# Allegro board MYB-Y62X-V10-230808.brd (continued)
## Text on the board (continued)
Ref Des/Silkscreen Bottom: LVDS0 | LVDS1 | SIM1 | SIM2 | CSI0
User.Comments: CR_3_1 | CR_1_1
Ref Des/Silkscreen Top: GND | TX | RX | VDD_12V | VDD_3V9 | VDD_5V | VDD_3V3 | VDD_1V8 | B2 | 1 | 0 | B3 | A2 | B4 | B5 | B6 | 485 | B1 | B7 | B8 | B9 | A1 | CAN | H2 | L2 | H1 | L1 | 1  0  0  1  0  0  0  EMMC Boot | 0  1  1  1  0  0  1  OSPI | 0  0  0  1  0  0  1  MMCSD Boot | B3 B4 B5 B6 B7 B8 B9 BOOTDEVICE | BACK LIGHT | Debug | DUAL_LVDS | WIFI | Bluetooth | MYB-Y62X-V10 | SOC Reset | MCU Reset | User | GPMC | JTAG | DC 12V | 4G ANT | AUDIO | USB0 | USB_UART | Micro SD | ENET1 | ENET2 | USB_HOST | HDMI
DIMENSION: 100 ohm | 90 ohm | 50 ohm | 1,6 | 1 | 3 | 18.0 | + | - | 5 | L2&L5 | L3 | L2
DISPLAY_BOTTOM: S0 | S2  S1  S0 | 1   0   1 | 1   0   0 | 0   0   0 | S1 | S2 | BootDevice | 3.3V QSPI | 1.8V EMMC | Download | 1 | 0 | OFF | ON | Debug | JTAG | UART 2 | ADC | GND | TXD | RXD | Reset | User | ONOFF | J13 | J14 | J15 | J12 | J19 | J18 | J11 | J5 | J4 | J7 | J3 | J20 | J21 | J8 | J1 | SW1 | J9 | J23 | J22 | J10 | WIFI | 4G ANT | WIFI ANT | Micro SD | USB | AUDIO | DC 12V | ENET1 | ENET0 | USB HOST | HDMI | MYB-YG2LX-V01
DEVICE_TYPE_BOTTOM: 1 | 2 | 6 | 10 | 3 | 9 | 75 | 74 | 21 | 20 | 11
User.16: FIGURE | SIZE | 8.0 | 10.0 | 19.69 | 23.62 | 27.56 | 35.43 | 36.22 | 43.31 | 47.24 | 53.15 | 62.99 | 86.61 | 109.0 | 125.0 | 125.98 | 21.65 | 41.34 | 43.0 | 63.0 | 118.11 | 127.95 | 40.16x31.5 | 47.24x23.62 | 55.12x19.69 | 62.99x23.62 | 70.87x23.62 | 70.87x51.18 | 78.74x23.62 | 78.74x31.5 | 82.68x39.37 | 106.3x39.37 | 62.99x62.99 | DRILL CHART: TOP to BOTTOM | ALL UNITS ARE IN MILS | TOLERANCE | +3.0/-3.0 | +0.0/-0.0 | +2.0/-2.0 | PLATED | NON-PLATED | QTY | 761 | 1788 | 32 | 1 | 8 | 47 | 12 | 4 | 2 | 6 | 3
